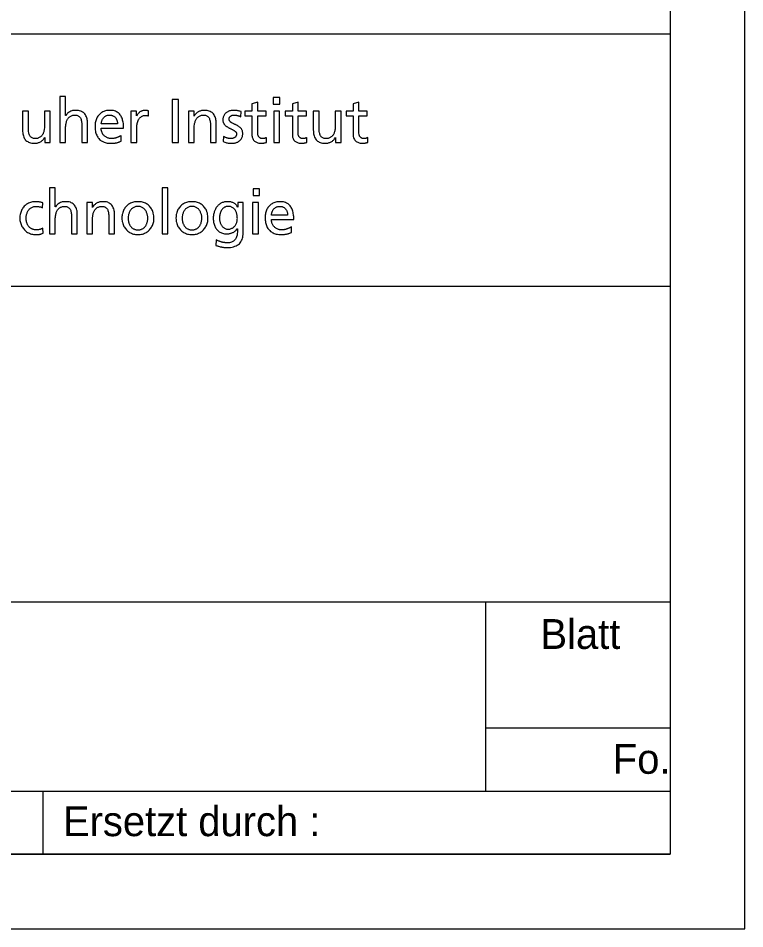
# Model space of a CAD drawing. Extents: x 0 to 119, y 0 to 84.
# Drawn here: x 109.07 to 118.8, y 0 to 12.21 of the extents above; entities that cross this region are included whole.
import ezdxf

# ---------------------------------------------------------------- set-up
doc = ezdxf.new("R2010")
doc.units = 0
doc.layers.add('90_Plankopf', color=7, linetype='Continuous')

msp = doc.modelspace()

# ---------------------------------------------------------------- linework, layer by layer
at = {"layer": '90_Plankopf'}
for p, q in [((117.8, 16.998), (117.8, 1)), ((82.224, 11.998), (117.8, 11.998)), ((82.224, 11.998), (117.8, 11.998)), ((117.8, 11.998), (117.8, 1)), ((110.811, 10.897), (110.811, 10.966)), ((112.046, 10.888), (112.053, 10.956)), ((110.394, 10.792), (110.177, 10.792)), ((110.177, 10.734), (110.477, 10.734)), ((110.445, 10.559), (110.445, 10.636)), ((111.814, 10.624), (111.81, 10.554)), ((112.392, 10.543), (112.392, 10.609)), ((112.933, 10.543), (112.933, 10.609)), ((113.749, 10.543), (113.749, 10.609)), ((109.39, 9.667), (109.397, 9.732)), ((112.675, 9.568), (112.457, 9.568)), ((112.457, 9.51), (112.757, 9.51)), ((112.725, 9.335), (112.725, 9.412)), ((109.4, 9.325), (109.394, 9.394)), ((111.719, 9.235), (111.711, 9.163)), ((101, 8.614), (117.8, 8.614)), ((101, 4.384), (117.8, 4.384)), ((115.329, 1.846), (115.329, 4.384)), ((115.329, 2.692), (117.8, 2.692)), ((101, 1.846), (117.8, 1.846)), ((109.4, 1), (109.4, 1.846)), ((117.8, 1), (82.224, 1)), ((84.56, 1), (117.8, 1)), ((84.56, 1), (117.8, 1))]:
    msp.add_line(p, q, dxfattribs=at)
for points in [[(0, 0), (118.8, 0), (118.8, 84), (0, 84)], [(5, 83), (117.8, 83), (117.8, 1), (5, 1)]]:
    msp.add_lwpolyline(points, close=True, dxfattribs=at)
for points in [[(109.702, 10.902), (109.7, 10.902), (109.7, 11.16), (109.623, 11.16), (109.623, 10.541), (109.7, 10.541), (109.7, 10.736)], [(111.129, 10.541), (111.212, 10.541), (111.212, 11.117), (111.129, 11.117), (111.129, 10.541)], [(112.571, 11.056), (112.571, 11.144), (112.483, 11.144), (112.483, 11.056), (112.571, 11.056)], [(112.274, 10.669), (112.274, 10.899), (112.386, 10.899), (112.386, 10.962), (112.274, 10.962), (112.274, 11.084), (112.197, 11.059), (112.197, 10.962), (112.102, 10.962), (112.102, 10.899), (112.197, 10.899), (112.197, 10.653)], [(112.815, 10.669), (112.815, 10.899), (112.927, 10.899), (112.927, 10.962), (112.815, 10.962), (112.815, 11.084), (112.738, 11.059), (112.738, 10.962), (112.643, 10.962), (112.643, 10.899), (112.738, 10.899), (112.738, 10.653)], [(113.631, 10.669), (113.631, 10.899), (113.742, 10.899), (113.742, 10.962), (113.631, 10.962), (113.631, 11.084), (113.553, 11.059), (113.553, 10.962), (113.458, 10.962), (113.458, 10.899), (113.553, 10.899), (113.553, 10.653)], [(109.201, 10.744), (109.201, 10.962), (109.123, 10.962), (109.123, 10.712)], [(109.419, 10.608), (109.42, 10.608), (109.42, 10.541), (109.495, 10.541), (109.495, 10.962), (109.418, 10.962), (109.418, 10.767)], [(110.65, 10.897), (110.649, 10.897), (110.649, 10.962), (110.576, 10.962), (110.576, 10.541), (110.654, 10.541), (110.654, 10.733)], [(111.423, 10.895), (111.422, 10.895), (111.422, 10.962), (111.346, 10.962), (111.346, 10.541), (111.424, 10.541), (111.424, 10.736)], [(112.488, 10.962), (112.488, 10.541), (112.566, 10.541), (112.566, 10.962), (112.488, 10.962)], [(113.097, 10.744), (113.097, 10.962), (113.019, 10.962), (113.019, 10.712)], [(113.315, 10.608), (113.316, 10.608), (113.316, 10.541), (113.391, 10.541), (113.391, 10.962), (113.314, 10.962), (113.314, 10.767)], [(109.917, 10.759), (109.917, 10.541), (109.995, 10.541), (109.995, 10.791)], [(111.641, 10.759), (111.641, 10.541), (111.719, 10.541), (111.719, 10.791)], [(109.564, 9.678), (109.562, 9.678), (109.562, 9.936), (109.484, 9.936), (109.484, 9.317), (109.562, 9.317), (109.562, 9.512)], [(110.993, 9.317), (111.07, 9.317), (111.07, 9.936), (110.993, 9.936), (110.993, 9.317)], [(112.299, 9.832), (112.299, 9.92), (112.211, 9.92), (112.211, 9.832), (112.299, 9.832)], [(110.061, 9.671), (110.059, 9.671), (110.059, 9.738), (109.984, 9.738), (109.984, 9.317), (110.061, 9.317), (110.061, 9.512)], [(112.079, 9.335), (112.079, 9.738), (112.007, 9.738), (112.007, 9.676), (112.006, 9.676)], [(112.206, 9.738), (112.206, 9.317), (112.284, 9.317), (112.284, 9.738), (112.206, 9.738)], [(109.779, 9.535), (109.779, 9.317), (109.857, 9.317), (109.857, 9.567)], [(110.279, 9.535), (110.279, 9.317), (110.356, 9.317), (110.356, 9.567)], [(112, 9.382), (112.001, 9.382), (112.001, 9.341)]]:
    msp.add_lwpolyline(points, dxfattribs=at)
for points in [[(109.7, 10.736), (109.7, 10.762), (109.703, 10.785), (109.708, 10.806), (109.713, 10.827), (109.721, 10.846), (109.731, 10.861), (109.742, 10.876), (109.755, 10.888), (109.771, 10.897), (109.787, 10.905), (109.806, 10.909), (109.828, 10.909), (109.851, 10.908), (109.868, 10.902), (109.881, 10.89), (109.895, 10.879), (109.904, 10.862), (109.909, 10.841), (109.915, 10.819), (109.917, 10.792), (109.917, 10.759)], [(109.995, 10.791), (109.995, 10.829), (109.989, 10.861), (109.978, 10.888), (109.967, 10.915), (109.95, 10.936), (109.927, 10.95), (109.903, 10.965), (109.874, 10.972), (109.837, 10.972), (109.808, 10.972), (109.781, 10.966), (109.758, 10.954), (109.735, 10.942), (109.716, 10.924), (109.702, 10.902)], [(110.477, 10.734), (110.477, 10.768), (110.474, 10.8), (110.468, 10.829), (110.461, 10.857), (110.451, 10.882), (110.437, 10.904), (110.422, 10.925), (110.403, 10.942), (110.38, 10.954), (110.356, 10.966), (110.326, 10.972), (110.291, 10.972), (110.261, 10.972), (110.235, 10.967), (110.21, 10.956), (110.186, 10.946), (110.165, 10.931), (110.148, 10.912), (110.131, 10.893), (110.117, 10.871), (110.108, 10.845), (110.099, 10.819), (110.094, 10.79), (110.094, 10.759), (110.094, 10.725), (110.098, 10.694), (110.107, 10.666), (110.116, 10.638), (110.129, 10.614), (110.147, 10.594), (110.165, 10.574), (110.187, 10.558), (110.215, 10.548), (110.242, 10.537), (110.275, 10.531), (110.312, 10.531), (110.335, 10.531), (110.354, 10.533), (110.371, 10.536), (110.387, 10.539), (110.401, 10.543), (110.413, 10.547), (110.424, 10.551), (110.435, 10.555), (110.445, 10.559)], [(110.177, 10.792), (110.178, 10.806), (110.181, 10.82), (110.186, 10.833), (110.191, 10.847), (110.198, 10.86), (110.207, 10.871), (110.216, 10.883), (110.227, 10.892), (110.241, 10.899), (110.254, 10.906), (110.271, 10.909), (110.29, 10.909), (110.306, 10.909), (110.321, 10.906), (110.334, 10.9), (110.347, 10.894), (110.358, 10.886), (110.367, 10.875), (110.376, 10.864), (110.383, 10.852), (110.387, 10.838), (110.392, 10.823), (110.394, 10.808), (110.394, 10.792)], [(110.811, 10.966), (110.806, 10.967), (110.801, 10.968), (110.796, 10.969), (110.791, 10.97), (110.786, 10.971), (110.78, 10.971), (110.774, 10.972), (110.768, 10.972), (110.76, 10.972), (110.745, 10.972), (110.731, 10.969), (110.716, 10.962), (110.702, 10.956), (110.69, 10.947), (110.678, 10.936), (110.667, 10.925), (110.657, 10.912), (110.65, 10.897)], [(110.654, 10.733), (110.654, 10.768), (110.659, 10.799), (110.668, 10.824), (110.678, 10.85), (110.691, 10.87), (110.708, 10.883), (110.725, 10.897), (110.745, 10.904), (110.768, 10.904), (110.775, 10.904), (110.782, 10.904), (110.79, 10.903), (110.797, 10.902), (110.804, 10.9), (110.811, 10.897)], [(111.719, 10.791), (111.719, 10.829), (111.713, 10.861), (111.702, 10.888), (111.691, 10.915), (111.674, 10.936), (111.65, 10.95), (111.627, 10.965), (111.597, 10.972), (111.561, 10.972), (111.541, 10.972), (111.522, 10.969), (111.504, 10.963), (111.486, 10.957), (111.47, 10.948), (111.456, 10.936), (111.442, 10.925), (111.431, 10.911), (111.423, 10.895)], [(111.424, 10.736), (111.424, 10.762), (111.426, 10.785), (111.432, 10.806), (111.437, 10.827), (111.444, 10.846), (111.455, 10.861), (111.465, 10.876), (111.479, 10.888), (111.495, 10.897), (111.511, 10.905), (111.53, 10.909), (111.552, 10.909), (111.574, 10.908), (111.592, 10.902), (111.605, 10.89), (111.618, 10.879), (111.627, 10.862), (111.633, 10.841), (111.639, 10.819), (111.641, 10.792), (111.641, 10.759)], [(112.053, 10.956), (112.038, 10.96), (112.022, 10.964), (112.007, 10.967), (111.991, 10.97), (111.974, 10.972), (111.956, 10.972), (111.936, 10.972), (111.916, 10.969), (111.898, 10.964), (111.88, 10.959), (111.864, 10.951), (111.851, 10.94), (111.837, 10.929), (111.827, 10.916), (111.819, 10.9), (111.812, 10.883), (111.808, 10.864), (111.808, 10.842), (111.808, 10.826), (111.811, 10.811), (111.818, 10.799), (111.825, 10.787), (111.833, 10.776), (111.844, 10.767), (111.855, 10.758), (111.867, 10.75), (111.88, 10.743), (111.893, 10.736), (111.906, 10.729), (111.919, 10.723), (111.931, 10.717), (111.943, 10.711), (111.954, 10.704), (111.965, 10.698), (111.974, 10.691), (111.98, 10.683), (111.987, 10.675), (111.99, 10.665), (111.99, 10.654), (111.99, 10.643), (111.988, 10.633), (111.983, 10.626), (111.978, 10.618), (111.972, 10.612), (111.964, 10.607), (111.956, 10.602), (111.948, 10.599), (111.938, 10.597), (111.929, 10.595), (111.92, 10.594), (111.911, 10.594), (111.903, 10.594), (111.894, 10.595), (111.883, 10.597), (111.872, 10.599), (111.86, 10.603), (111.848, 10.607), (111.836, 10.612), (111.825, 10.617), (111.814, 10.624)], [(111.81, 10.554), (111.828, 10.545), (111.847, 10.539), (111.867, 10.536), (111.886, 10.532), (111.906, 10.531), (111.926, 10.531), (111.945, 10.531), (111.963, 10.534), (111.98, 10.539), (111.998, 10.544), (112.014, 10.552), (112.028, 10.563), (112.041, 10.574), (112.052, 10.588), (112.06, 10.604), (112.069, 10.621), (112.073, 10.64), (112.073, 10.662), (112.073, 10.682), (112.069, 10.698), (112.063, 10.711), (112.056, 10.724), (112.047, 10.736), (112.037, 10.745), (112.026, 10.754), (112.014, 10.762), (112.001, 10.769), (111.988, 10.776), (111.975, 10.782), (111.962, 10.787), (111.949, 10.793), (111.937, 10.799), (111.927, 10.805), (111.916, 10.812), (111.907, 10.819), (111.9, 10.827), (111.894, 10.836), (111.891, 10.846), (111.89, 10.858), (111.891, 10.87), (111.894, 10.879), (111.901, 10.887), (111.908, 10.894), (111.917, 10.9), (111.928, 10.904), (111.939, 10.908), (111.951, 10.909), (111.965, 10.909), (111.969, 10.909), (111.975, 10.909), (111.983, 10.908), (111.99, 10.906), (111.998, 10.905), (112.006, 10.903), (112.014, 10.901), (112.022, 10.898), (112.029, 10.896), (112.036, 10.893), (112.042, 10.891), (112.046, 10.888)], [(109.418, 10.767), (109.418, 10.742), (109.415, 10.718), (109.41, 10.697), (109.405, 10.676), (109.398, 10.658), (109.387, 10.642), (109.377, 10.627), (109.363, 10.615), (109.347, 10.607), (109.331, 10.598), (109.312, 10.594), (109.29, 10.594), (109.268, 10.595), (109.25, 10.602), (109.237, 10.613), (109.224, 10.624), (109.214, 10.641), (109.209, 10.662), (109.203, 10.684), (109.201, 10.711), (109.201, 10.744)], [(113.314, 10.767), (113.314, 10.742), (113.311, 10.718), (113.306, 10.697), (113.301, 10.676), (113.293, 10.658), (113.283, 10.642), (113.272, 10.627), (113.259, 10.615), (113.243, 10.607), (113.227, 10.598), (113.208, 10.594), (113.186, 10.594), (113.163, 10.595), (113.146, 10.602), (113.133, 10.613), (113.119, 10.624), (113.11, 10.641), (113.105, 10.662), (113.099, 10.684), (113.097, 10.711), (113.097, 10.744)], [(109.123, 10.712), (109.123, 10.674), (109.129, 10.642), (109.14, 10.615), (109.151, 10.588), (109.168, 10.567), (109.192, 10.553), (109.215, 10.539), (109.245, 10.531), (109.281, 10.531), (109.301, 10.531), (109.32, 10.534), (109.338, 10.54), (109.356, 10.547), (109.372, 10.555), (109.386, 10.567), (109.4, 10.578), (109.411, 10.592), (109.419, 10.608)], [(110.445, 10.636), (110.44, 10.632), (110.433, 10.628), (110.424, 10.623), (110.415, 10.618), (110.404, 10.614), (110.392, 10.609), (110.38, 10.605), (110.368, 10.601), (110.354, 10.598), (110.341, 10.596), (110.328, 10.594), (110.315, 10.594), (110.297, 10.594), (110.279, 10.597), (110.263, 10.604), (110.246, 10.611), (110.231, 10.621), (110.218, 10.633), (110.205, 10.645), (110.195, 10.66), (110.188, 10.677), (110.181, 10.694), (110.177, 10.713), (110.177, 10.734)], [(112.197, 10.653), (112.197, 10.625), (112.202, 10.602), (112.213, 10.584), (112.223, 10.566), (112.238, 10.553), (112.257, 10.544), (112.277, 10.536), (112.299, 10.531), (112.326, 10.531), (112.339, 10.531), (112.351, 10.533), (112.362, 10.535), (112.373, 10.538), (112.384, 10.54), (112.392, 10.543)], [(112.392, 10.609), (112.387, 10.605), (112.379, 10.602), (112.371, 10.599), (112.362, 10.596), (112.351, 10.594), (112.34, 10.594), (112.328, 10.594), (112.317, 10.597), (112.307, 10.603), (112.297, 10.608), (112.289, 10.617), (112.283, 10.628), (112.277, 10.639), (112.274, 10.653), (112.274, 10.669)], [(112.738, 10.653), (112.738, 10.625), (112.743, 10.602), (112.753, 10.584), (112.764, 10.566), (112.779, 10.553), (112.798, 10.544), (112.817, 10.536), (112.84, 10.531), (112.867, 10.531), (112.88, 10.531), (112.892, 10.533), (112.903, 10.535), (112.914, 10.538), (112.924, 10.54), (112.933, 10.543)], [(112.933, 10.609), (112.927, 10.605), (112.92, 10.602), (112.911, 10.599), (112.903, 10.596), (112.892, 10.594), (112.88, 10.594), (112.868, 10.594), (112.857, 10.597), (112.848, 10.603), (112.838, 10.608), (112.83, 10.617), (112.824, 10.628), (112.818, 10.639), (112.815, 10.653), (112.815, 10.669)], [(113.019, 10.712), (113.019, 10.674), (113.025, 10.642), (113.036, 10.615), (113.047, 10.588), (113.064, 10.567), (113.087, 10.553), (113.111, 10.539), (113.14, 10.531), (113.177, 10.531), (113.196, 10.531), (113.215, 10.534), (113.233, 10.54), (113.251, 10.547), (113.267, 10.555), (113.282, 10.567), (113.296, 10.578), (113.307, 10.592), (113.315, 10.608)], [(113.553, 10.653), (113.553, 10.625), (113.559, 10.602), (113.569, 10.584), (113.579, 10.566), (113.594, 10.553), (113.614, 10.544), (113.633, 10.536), (113.656, 10.531), (113.683, 10.531), (113.695, 10.531), (113.707, 10.533), (113.718, 10.535), (113.73, 10.538), (113.74, 10.54), (113.749, 10.543)], [(113.749, 10.609), (113.743, 10.605), (113.736, 10.602), (113.727, 10.599), (113.718, 10.596), (113.708, 10.594), (113.696, 10.594), (113.684, 10.594), (113.673, 10.597), (113.663, 10.603), (113.653, 10.608), (113.646, 10.617), (113.64, 10.628), (113.634, 10.639), (113.631, 10.653), (113.631, 10.669)], [(109.397, 9.732), (109.389, 9.735), (109.38, 9.737), (109.37, 9.74), (109.359, 9.742), (109.348, 9.744), (109.336, 9.746), (109.324, 9.747), (109.313, 9.748), (109.303, 9.748), (109.27, 9.748), (109.241, 9.742), (109.215, 9.732), (109.189, 9.721), (109.166, 9.706), (109.147, 9.686), (109.128, 9.666), (109.114, 9.643), (109.104, 9.616), (109.093, 9.589), (109.088, 9.56), (109.088, 9.528), (109.088, 9.498), (109.094, 9.469), (109.104, 9.442), (109.114, 9.416), (109.129, 9.393), (109.148, 9.372), (109.167, 9.352), (109.189, 9.336), (109.216, 9.325), (109.242, 9.313), (109.271, 9.308), (109.303, 9.307), (109.312, 9.307), (109.322, 9.308), (109.333, 9.309), (109.344, 9.309), (109.355, 9.311), (109.367, 9.314), (109.378, 9.316), (109.389, 9.32), (109.4, 9.325)], [(109.394, 9.394), (109.386, 9.389), (109.377, 9.384), (109.368, 9.381), (109.359, 9.377), (109.349, 9.375), (109.339, 9.373), (109.329, 9.371), (109.32, 9.37), (109.311, 9.37), (109.291, 9.37), (109.273, 9.373), (109.258, 9.379), (109.243, 9.385), (109.23, 9.393), (109.218, 9.404), (109.207, 9.414), (109.198, 9.426), (109.191, 9.44), (109.184, 9.453), (109.179, 9.467), (109.176, 9.482), (109.172, 9.498), (109.171, 9.513), (109.171, 9.528), (109.171, 9.548), (109.174, 9.568), (109.18, 9.586), (109.186, 9.605), (109.194, 9.622), (109.206, 9.637), (109.217, 9.652), (109.231, 9.663), (109.248, 9.672), (109.265, 9.681), (109.284, 9.685), (109.306, 9.685), (109.319, 9.685), (109.332, 9.684), (109.346, 9.681), (109.361, 9.678), (109.375, 9.673), (109.39, 9.667)], [(109.562, 9.512), (109.562, 9.538), (109.565, 9.561), (109.57, 9.582), (109.575, 9.604), (109.582, 9.622), (109.593, 9.637), (109.603, 9.653), (109.617, 9.664), (109.633, 9.673), (109.649, 9.681), (109.668, 9.685), (109.69, 9.685), (109.712, 9.684), (109.73, 9.678), (109.743, 9.666), (109.756, 9.655), (109.765, 9.639), (109.771, 9.617), (109.777, 9.595), (109.779, 9.568), (109.779, 9.535)], [(109.857, 9.567), (109.857, 9.605), (109.851, 9.638), (109.84, 9.665), (109.829, 9.691), (109.812, 9.712), (109.788, 9.726), (109.765, 9.741), (109.735, 9.748), (109.699, 9.748), (109.669, 9.748), (109.643, 9.742), (109.62, 9.73), (109.597, 9.718), (109.578, 9.7), (109.564, 9.678)], [(110.356, 9.567), (110.356, 9.605), (110.351, 9.638), (110.339, 9.665), (110.328, 9.691), (110.311, 9.712), (110.288, 9.726), (110.265, 9.741), (110.235, 9.748), (110.198, 9.748), (110.179, 9.748), (110.16, 9.745), (110.142, 9.739), (110.124, 9.733), (110.108, 9.724), (110.094, 9.712), (110.08, 9.701), (110.068, 9.687), (110.061, 9.671)], [(110.061, 9.512), (110.061, 9.538), (110.064, 9.561), (110.069, 9.582), (110.074, 9.604), (110.082, 9.622), (110.092, 9.637), (110.103, 9.653), (110.116, 9.664), (110.132, 9.673), (110.148, 9.681), (110.167, 9.685), (110.189, 9.685), (110.212, 9.684), (110.23, 9.678), (110.243, 9.666), (110.256, 9.655), (110.265, 9.639), (110.27, 9.617), (110.276, 9.595), (110.279, 9.568), (110.279, 9.535)], [(110.879, 9.578), (110.876, 9.591), (110.873, 9.604), (110.868, 9.616), (110.858, 9.643), (110.844, 9.666), (110.825, 9.686), (110.806, 9.706), (110.783, 9.721), (110.757, 9.732), (110.731, 9.742), (110.702, 9.748), (110.67, 9.748), (110.638, 9.748), (110.608, 9.742), (110.582, 9.732), (110.556, 9.721), (110.533, 9.706), (110.514, 9.686), (110.495, 9.666), (110.481, 9.643), (110.471, 9.616), (110.46, 9.589), (110.455, 9.56), (110.455, 9.528)], [(110.538, 9.528), (110.538, 9.548), (110.541, 9.568), (110.547, 9.586), (110.553, 9.605), (110.561, 9.622), (110.573, 9.637), (110.584, 9.652), (110.598, 9.663), (110.614, 9.672), (110.63, 9.681), (110.649, 9.685), (110.67, 9.685), (110.69, 9.685), (110.709, 9.681), (110.725, 9.672), (110.741, 9.663), (110.755, 9.652), (110.766, 9.637), (110.778, 9.622), (110.786, 9.605), (110.792, 9.586), (110.798, 9.568), (110.801, 9.548), (110.801, 9.528), (110.801, 9.513), (110.799, 9.498), (110.796, 9.482), (110.793, 9.467), (110.788, 9.453), (110.781, 9.44), (110.774, 9.426), (110.766, 9.414), (110.755, 9.404), (110.745, 9.393), (110.733, 9.385), (110.718, 9.379), (110.704, 9.373), (110.688, 9.37), (110.67, 9.37), (110.652, 9.37), (110.635, 9.373), (110.621, 9.379), (110.607, 9.385), (110.594, 9.393), (110.584, 9.404), (110.573, 9.414), (110.565, 9.426), (110.558, 9.44), (110.551, 9.453), (110.546, 9.467), (110.543, 9.482), (110.539, 9.498), (110.538, 9.513), (110.538, 9.528)], [(111.603, 9.578), (111.6, 9.591), (111.597, 9.604), (111.592, 9.616), (111.582, 9.643), (111.568, 9.666), (111.549, 9.686), (111.53, 9.706), (111.507, 9.721), (111.481, 9.732), (111.455, 9.742), (111.426, 9.748), (111.394, 9.748), (111.362, 9.748), (111.332, 9.742), (111.306, 9.732), (111.28, 9.721), (111.257, 9.706), (111.238, 9.686), (111.219, 9.666), (111.205, 9.643), (111.195, 9.616), (111.185, 9.589), (111.179, 9.56), (111.179, 9.528)], [(111.262, 9.528), (111.262, 9.548), (111.265, 9.568), (111.271, 9.586), (111.277, 9.605), (111.285, 9.622), (111.297, 9.637), (111.308, 9.652), (111.322, 9.663), (111.338, 9.672), (111.354, 9.681), (111.373, 9.685), (111.394, 9.685), (111.415, 9.685), (111.433, 9.681), (111.449, 9.672), (111.465, 9.663), (111.479, 9.652), (111.49, 9.637), (111.502, 9.622), (111.51, 9.605), (111.516, 9.586), (111.522, 9.568), (111.525, 9.548), (111.525, 9.528), (111.525, 9.513), (111.523, 9.498), (111.52, 9.482), (111.517, 9.467), (111.512, 9.453), (111.505, 9.44), (111.498, 9.426), (111.49, 9.414), (111.479, 9.404), (111.469, 9.393), (111.457, 9.385), (111.442, 9.379), (111.428, 9.373), (111.412, 9.37), (111.394, 9.37), (111.376, 9.37), (111.359, 9.373), (111.345, 9.379), (111.331, 9.385), (111.318, 9.393), (111.308, 9.404), (111.297, 9.414), (111.289, 9.426), (111.282, 9.44), (111.275, 9.453), (111.27, 9.467), (111.267, 9.482), (111.263, 9.498), (111.262, 9.513), (111.262, 9.528)], [(112.006, 9.676), (111.998, 9.691), (111.988, 9.704), (111.976, 9.715), (111.964, 9.725), (111.949, 9.734), (111.931, 9.739), (111.913, 9.745), (111.891, 9.748), (111.867, 9.748), (111.841, 9.748), (111.819, 9.744), (111.799, 9.735), (111.778, 9.727), (111.761, 9.715), (111.746, 9.7), (111.731, 9.686), (111.718, 9.669), (111.708, 9.65), (111.698, 9.631), (111.691, 9.611), (111.686, 9.589), (111.681, 9.568), (111.679, 9.546), (111.679, 9.524), (111.679, 9.497), (111.682, 9.471), (111.69, 9.446), (111.697, 9.421), (111.709, 9.399), (111.724, 9.38), (111.738, 9.361), (111.757, 9.345), (111.78, 9.334), (111.802, 9.323), (111.829, 9.318), (111.859, 9.317), (111.877, 9.317), (111.894, 9.32), (111.912, 9.324), (111.929, 9.329), (111.945, 9.337), (111.96, 9.346), (111.976, 9.356), (111.989, 9.368), (112, 9.382)], [(111.878, 9.38), (111.86, 9.38), (111.844, 9.384), (111.83, 9.392), (111.815, 9.4), (111.803, 9.411), (111.793, 9.425), (111.782, 9.438), (111.775, 9.454), (111.769, 9.472), (111.764, 9.49), (111.761, 9.509), (111.761, 9.529), (111.761, 9.543), (111.763, 9.558), (111.766, 9.572), (111.769, 9.587), (111.774, 9.601), (111.78, 9.615), (111.786, 9.628), (111.794, 9.64), (111.803, 9.651), (111.813, 9.661), (111.824, 9.67), (111.836, 9.676), (111.849, 9.682), (111.863, 9.685), (111.878, 9.685), (111.899, 9.685), (111.917, 9.681), (111.933, 9.672), (111.948, 9.664), (111.961, 9.652), (111.971, 9.637), (111.981, 9.622), (111.989, 9.605), (111.994, 9.585), (111.999, 9.566), (112.001, 9.545), (112.001, 9.523), (112.001, 9.503), (111.998, 9.485), (111.993, 9.467), (111.987, 9.45), (111.978, 9.435), (111.967, 9.422), (111.956, 9.409), (111.943, 9.399), (111.928, 9.391), (111.913, 9.384), (111.897, 9.38), (111.878, 9.38)], [(112.757, 9.51), (112.757, 9.544), (112.754, 9.576), (112.748, 9.605), (112.742, 9.634), (112.731, 9.659), (112.717, 9.68), (112.702, 9.701), (112.683, 9.718), (112.66, 9.73), (112.636, 9.742), (112.606, 9.748), (112.571, 9.748), (112.542, 9.748), (112.515, 9.743), (112.49, 9.732), (112.466, 9.722), (112.445, 9.707), (112.428, 9.688), (112.411, 9.669), (112.397, 9.647), (112.388, 9.621), (112.379, 9.595), (112.374, 9.567), (112.374, 9.535), (112.374, 9.501), (112.378, 9.47), (112.387, 9.442), (112.396, 9.414), (112.409, 9.39), (112.427, 9.37), (112.445, 9.35), (112.468, 9.334), (112.495, 9.324), (112.522, 9.313), (112.555, 9.308), (112.592, 9.307), (112.615, 9.308), (112.634, 9.309), (112.651, 9.312), (112.667, 9.315), (112.681, 9.319), (112.693, 9.323), (112.704, 9.327), (112.715, 9.331), (112.725, 9.335)], [(112.457, 9.568), (112.458, 9.582), (112.461, 9.596), (112.466, 9.609), (112.471, 9.623), (112.478, 9.636), (112.487, 9.647), (112.496, 9.659), (112.507, 9.668), (112.521, 9.675), (112.534, 9.682), (112.551, 9.685), (112.57, 9.685), (112.586, 9.685), (112.601, 9.682), (112.614, 9.676), (112.627, 9.67), (112.638, 9.662), (112.647, 9.651), (112.656, 9.64), (112.663, 9.628), (112.668, 9.614), (112.672, 9.6), (112.675, 9.584), (112.675, 9.568)], [(110.455, 9.528), (110.455, 9.498), (110.461, 9.469), (110.471, 9.442), (110.481, 9.416), (110.496, 9.393), (110.515, 9.372), (110.534, 9.352), (110.556, 9.336), (110.583, 9.325), (110.609, 9.313), (110.638, 9.308), (110.67, 9.307), (110.701, 9.308), (110.731, 9.313), (110.756, 9.325), (110.783, 9.336), (110.805, 9.352), (110.824, 9.372), (110.843, 9.393), (110.858, 9.416), (110.868, 9.442), (110.878, 9.469), (110.883, 9.498), (110.884, 9.528), (110.884, 9.545), (110.882, 9.562), (110.879, 9.578)], [(111.179, 9.528), (111.179, 9.498), (111.185, 9.469), (111.195, 9.442), (111.205, 9.416), (111.22, 9.393), (111.239, 9.372), (111.258, 9.352), (111.281, 9.336), (111.307, 9.325), (111.333, 9.313), (111.362, 9.308), (111.394, 9.307), (111.426, 9.308), (111.455, 9.313), (111.481, 9.325), (111.507, 9.336), (111.529, 9.352), (111.548, 9.372), (111.567, 9.393), (111.582, 9.416), (111.592, 9.442), (111.602, 9.469), (111.607, 9.498), (111.608, 9.528), (111.608, 9.545), (111.606, 9.562), (111.603, 9.578)], [(112.725, 9.412), (112.72, 9.408), (112.713, 9.404), (112.704, 9.399), (112.695, 9.394), (112.684, 9.39), (112.672, 9.385), (112.66, 9.381), (112.648, 9.377), (112.634, 9.374), (112.621, 9.372), (112.608, 9.37), (112.595, 9.37), (112.577, 9.37), (112.559, 9.374), (112.543, 9.38), (112.526, 9.387), (112.511, 9.397), (112.498, 9.409), (112.486, 9.421), (112.475, 9.436), (112.468, 9.453), (112.461, 9.471), (112.457, 9.49), (112.457, 9.51)], [(111.711, 9.163), (111.733, 9.155), (111.753, 9.149), (111.77, 9.145), (111.787, 9.141), (111.803, 9.138), (111.818, 9.136), (111.833, 9.135), (111.847, 9.134), (111.862, 9.134), (111.912, 9.134), (111.953, 9.142), (111.985, 9.158), (112.017, 9.174), (112.041, 9.196), (112.056, 9.226), (112.072, 9.256), (112.079, 9.293), (112.079, 9.335)], [(112.001, 9.341), (112.001, 9.311), (111.996, 9.286), (111.986, 9.264), (111.975, 9.243), (111.961, 9.226), (111.941, 9.214), (111.922, 9.203), (111.898, 9.197), (111.871, 9.197), (111.857, 9.197), (111.844, 9.197), (111.832, 9.199), (111.819, 9.2), (111.808, 9.203), (111.796, 9.206), (111.784, 9.209), (111.772, 9.212), (111.76, 9.217), (111.747, 9.222), (111.734, 9.228), (111.719, 9.235)]]:
    msp.add_open_spline(points, degree=3, dxfattribs=at)

# ---------------------------------------------------------------- texts
for s, p in [('Blatt', (116.063, 3.752)), ('Fo.', (117.032, 2.078)), ('Ersetzt durch :', (109.665, 1.242))]:
    msp.add_text(s, height=0.4, dxfattribs=at).set_placement(p)

doc.saveas('drawing.dxf')
